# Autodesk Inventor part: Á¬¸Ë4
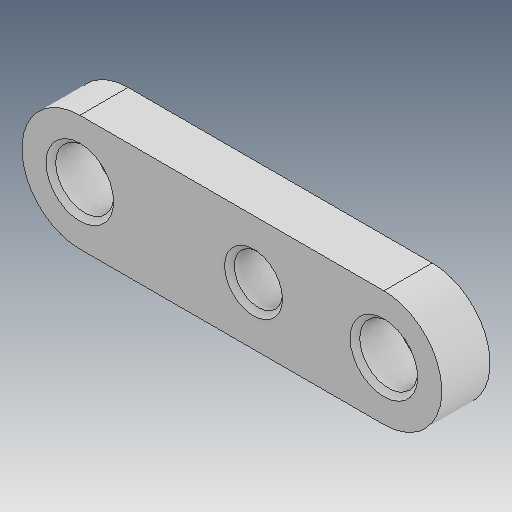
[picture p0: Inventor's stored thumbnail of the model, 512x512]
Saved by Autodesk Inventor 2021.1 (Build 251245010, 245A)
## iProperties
Created: 2015-08
Part Number: Á¬¸Ë4
Material: Ogólny
Document SubType Name: Modeling
Designer: user
Density: 1 g/cm^3
Appearance: Domyślna
Author: user
Revision Number: ÈÎºÎ
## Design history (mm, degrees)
feature "µ¹½Ç1"
node "Bryła1"
